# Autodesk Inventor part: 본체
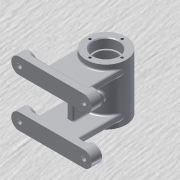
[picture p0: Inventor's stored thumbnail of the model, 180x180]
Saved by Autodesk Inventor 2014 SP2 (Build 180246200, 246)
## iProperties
Created: 2015-11
Part Number: 본체
Material: 알루미늄 6061
Document SubType Name: Modeling
Designer: 702
Density: 2.71 g/cm^3
Appearance: 알루미늄 - 평지
Mass: 359.113 g
Surface Area: 459.595 cm^2
Volume: 132.514 cm^3
Author: 702
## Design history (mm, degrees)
sketch "스케치1"
  geometry: C1 r 25 at (0, 0); 1 further point
  constraints: 1 centre point, 1 coincident
  dimensions: "d0" = 50 diameter of C1
extrude "돌출1" new body sketch "스케치1" stored distance "d1" = 70; taper "d2" = 0 deg
node "작업 평면1"
sketch "스케치2"
  geometry: L1 (-25, 0)-(-25, -58); L2 (-25, -58)-(25, -58); L3 (25, -58)-(25, 0); A1 r 25 centre (0, 0) between (-25, 0) and (25, 0) reference; A2 r 25 centre (0, 0) between (-25, 0) and (25, 0); 1 further point
  constraints: 6 end point, 4 point on circle, 2 tangent, 1 centre point, 1 coincident, 1 concentric, 1 perpendicular, 1 vertical
  dimensions: "d4" = 50 distance of L1.end L2.end; "d5" = 58 distance of L1.start L1.end
extrude "돌출2" join sketch "스케치2" distance "d6" = 8; taper "d7" = 0 deg
sketch "스케치3"
  geometry: L1 (0, 0)-(50, 0) reference; L2 (50, 0)-(50, 8) reference; L3 (0, 8)-(50, 8) reference; L4 (0, 0)-(0, 8) reference; L5 (65, 0)-(-15, 0); L6 (-15, 20)-(65, 20); A1 r 10 centre (-15, 10) between (-15, 20) and (-15, 0); A2 r 10 centre (65, 10) between (65, 0) and (65, 20); 2 further points
  constraints: 4 end point, 4 point on circle, 4 tangent, 2 centre point, 2 point on line, 1 midpoint, 1 parallel, 1 vertical alignment
  dimensions: "d8" = 20 distance between parallel lines of L5 L6; "d9" = 80 distance of A2.centre A1.centre
extrude "돌출3" join sketch "스케치3" distance "d10" = 10; taper "d11" = 0 deg
sketch "스케치4"
  geometry: C1 r 10 at (-15, -10); C2 r 10 at (65, -10); A1 r 10 centre (-15, -10) between (-15, 0) and (-15, -20) reference; A2 r 10 centre (65, -10) between (65, -20) and (65, 0) reference; 1 further point
  constraints: 2 centre point, 2 coincident, 1 equal radius
  dimensions: "d12" = 20 diameter of C1
extrude "돌출4" join sketch "스케치4" distance "d13" = 3; taper "d14" = 0 deg
hole "구멍1" diameter "d17" = 6; stored, may be unused: countersink angle "d21" = 90 deg, drill point angle "d23" = 118 deg; dims "d15" = 10, "d16" = 10, "d18" = 6, "d19" = 12, "d20" = 4, "d22" = 8
fillet "모깎기1" dims "d24" = 0.3
chamfer "모따기1" distance "d25" = 1; stored, may be unused: second distance "d26" = 2, angle "d27" = 45 deg
sketch "스케치5"
  geometry: L1 (-25, -35)-(-25, 35) reference; L2 (0, 20)-(-58, 20) reference; L3 (0, -20)-(-58, -20) reference; L4 (-45, 23.977)-(-45, -23.977); L5 (-45, 23.977)-(-20.486, 23.977); L6 (-20.486, 23.977)-(-20.486, -23.977); L7 (-20.486, -23.977)-(-45, -23.977); 2 further points
  constraints: 8 end point, 2 parallel, 2 perpendicular, 1 horizontal alignment, 1 midpoint
  dimensions: "d28" = 20 distance between parallel lines of L1 L4; "d29" = 47.95318 distance of L4.start L4.end; "d30" = 24.51379 distance between parallel lines of L4 L6
extrude "돌출5" join sketch "스케치5" stored distance "d31" = 8; taper "d32" = 0 deg
sketch "스케치6"
  geometry: L1 (-20, -24.678)-(20, -24.678) reference; L2 (-8, -35)-(8, -35); L3 (-8, -38.5)-(8, -38.5); L4 (8, -31.5)-(-8, -31.5); L5 (33, -68)-(27, -68) reference; A1 r 3.5 centre (-8, -35) between (-8, -31.5) and (-8, -38.5); A2 r 3.5 centre (8, -35) between (8, -38.5) and (8, -31.5); 2 further points
  constraints: 8 end point, 4 point on circle, 4 tangent, 2 centre point, 2 parallel, 1 midpoint, 1 vertical alignment
  dimensions: "d33" = 3.5 radius of A2; "d34" = 23 dimension on A1 A2; "d35" = 33 distance from line of L5 L2.end
extrude "돌출6" cut sketch "스케치6" stored distance "d36" = 8; taper "d37" = 0 deg
hole "구멍2" diameter "d40" = 32; stored, may be unused: countersink angle "d44" = 90 deg, drill point angle "d46" = 0 deg; dims "d38" = 10, "d39" = 10, "d41" = 6, "d42" = 12, "d43" = 4, "d45" = 12
hole "구멍3" diameter "d49" = 28; stored, may be unused: countersink angle "d53" = 90 deg, drill point angle "d55" = 0 deg; dims "d47" = 10, "d48" = 10, "d50" = 6, "d51" = 12, "d52" = 4, "d54" = 2
hole "구멍4" diameter "d58" = 42; stored, may be unused: countersink angle "d62" = 90 deg, drill point angle "d64" = 0 deg; dims "d56" = 10, "d57" = 10, "d59" = 6, "d60" = 12, "d61" = 4, "d63" = 42
sketch "스케치7"
  geometry: C1 r 16 at (0, 0) reference; 1 further point
  constraints: 1 vertical alignment
  dimensions: "d65" = 20 distance of C1.centre point (0, 20)
hole "구멍5" sketch "스케치7" at (0, 20) diameter "d66" = 3.242; stored, may be unused: countersink angle "d70" = 90 deg, drill point angle "d72" = 118 deg; dims "d67" = 8, "d68" = 12, "d69" = 4, "d71" = 10
sketch "스케치8"
  geometry: L1 (22.307, 5)-(28, 5); L2 (28, 5)-(28, 0); L3 (28, 0)-(22.307, 0); L4 (22.307, 0)-(22.307, 5); L5 (25, -35)-(25, 35) reference; 1 further point
  constraints: 8 end point, 2 perpendicular, 1 horizontal, 1 horizontal alignment, 1 parallel
  dimensions: "d76" = 5 distance of L1.end L2.end; "d77" = 3 distance between parallel lines of L5 L2; "d78" = 5.69299 distance of L2.end L3.end
revolve "회전1" sketch "스케치8" stored, may be unused: angle "d79" = 90 deg
hole "구멍6" diameter "d82" = 5.188; stored, may be unused: countersink angle "d86" = 90 deg, drill point angle "d88" = 118 deg; dims "d80" = 10, "d81" = 10, "d83" = 8, "d84" = 12, "d85" = 4, "d87" = 10
sketch "스케치9"
  geometry: L1 (0, 0)-(7.164, 0); L2 (0, 0)-(14, -24.249); L3 (14, -24.249)-(19.196, -21.249); L4 (19.196, -21.249)-(16.578, -16.715); L5 (16.578, -16.715)-(11.382, -19.715)
  constraints: 10 end point, 3 perpendicular, 1 horizontal, 1 point on line
  dimensions: "d89" = 60 deg angle of L1 L2; "d90" = 28 distance of L1.start L2.end; "d91" = 6 distance of L2.end L3.end; "d92" = 5.23539 distance of L3.end L4.end
revolve "회전2" sketch "스케치9" stored, may be unused: angle "d93" = 90 deg
hole "구멍7" diameter "d96" = 5.188; stored, may be unused: countersink angle "d100" = 90 deg, drill point angle "d102" = 118 deg; dims "d94" = 10, "d95" = 10, "d97" = 8, "d98" = 12, "d99" = 4, "d101" = 10
node "작업 평면2"
sketch "스케치10"
  geometry: L1 (-25, -35)-(25, -35) reference; L2 (-25, -35)-(-25, 35) reference; 2 further points
  constraints: 1 other
  dimensions: "d103" = 35 distance from line of L1 point (0, 0); "d104" = 25 distance from line of point (0, 0) L2
feature "엠보싱1" sketch "스케치10" dims "d0" = 50, "d105" = 0.5, "d106" = 0
fillet "모깎기2" dims "d107" = 0.3
fillet "모깎기3" dims "d108" = 3
fillet "모깎기4" dims "d109" = 2
fillet "모깎기5" dims "d110" = 2
fillet "모깎기6" dims "d111" = 2
fillet "모깎기7" dims "d112" = 2
chamfer "모따기2" distance "d113" = 1; stored, may be unused: second distance "d114" = 2, angle "d115" = 45 deg
node "솔리드1"
mirror "대칭1"
mirror "대칭2"
mirror "대칭3"
pattern_circular "원형 패턴1" dims angle "d74" = 360 deg
mirror "대칭4"
